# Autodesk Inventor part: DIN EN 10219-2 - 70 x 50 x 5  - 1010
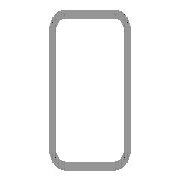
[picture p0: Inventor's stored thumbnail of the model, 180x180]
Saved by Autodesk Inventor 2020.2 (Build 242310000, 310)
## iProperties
_CCFamilyMember: 17
_CCFamilyDisplayName: DIN EN 10219-2 (Rechteckiges Hohlprofil - Kaltgeformt) - Kaltgeformte, geschweißte Baustahl-Hohlprofile aus unlegiertem Feinkorn-Baustahl
_FrameMemberDoc: Frame Member File
_Version: 15.0.0
_GetPNFromCC: 1
Created: 2019-01
Part Number: DIN EN 10219-2 - 70 x 50 x 5  - 1010
Material: Stahl, weich
Description: Kaltgeformte, geschweißte Baustahl-Hohlprofile aus unlegiertem Feinkorn-Baustahl
Document SubType Name: Modeling
Standard: DIN
Designer: lutzd
Standard Revision: 2006-07
Standards Organization: DIN
Language: de-DE
Size Designation: 70 x 50 x 5
Categories: <MemberInstance><Categories><Category DisplayName="Profile" InternalName="089c4875-fa83-4c05-b084-43b9cc11f5ed" Mnemonic="GRDR"><CategoryParameter DisplayName="
Stock Number: 70 x 50 x 5
Mass: 8208.18 g
Surface Area: 4205.32 cm^2
Volume: 1045.63 cm^3
Density: 7.85 g/cm^3
Appearance: Semi-Polished(8)
G_L: 1010,000 mm
G_W: 50,000 mm
G_H: 70,000 mm
DocNumber: ADSK-014374
Folder: .
Mass: 8,208 kg
VLT_Material: Stahl, weich
+F87BCFAC-049D-4AF7-812F-EB7A9C2FA896+SCHNITTDETAIL1: Schnittwinkel 90,00 grd
+55874402-68F4-4B5A-B811-96521EF574D8+SCHNITTDETAIL2: Schnittwinkel 90,00 grd
Dimensions: 50x70x1010 mm
IsCustomPart: 1
Title: Profil-Bauteil
Author: lutzd
Revision Number: -
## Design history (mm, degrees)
node "Startebene"
node "Endebene"
sketch "Skizze"
  geometry: L1 (-25, -25)-(-25, 25); L2 (-15, 35)-(15, 35); L3 (25, 25)-(25, -25); L4 (15, -35)-(-15, -35); L5 (-15, 30)-(15, 30); L6 (20, 25)-(20, -25); L7 (15, -30)-(-15, -30); L8 (-20, -25)-(-20, 25); L9 (0, 51.899)-(0, -51.899) reference; L10 (-37.899, 0)-(37.899, 0) reference; A1 r 10 centre (-15, -25) between (-25, -25) and (-15, -35); A2 r 10 centre (-15, 25) between (-15, 35) and (-25, 25); A3 r 10 centre (15, 25) between (25, 25) and (15, 35); A4 r 10 centre (15, -25) between (15, -35) and (25, -25); A5 r 5 centre (-15, 25) between (-15, 30) and (-20, 25); A6 r 5 centre (15, 25) between (20, 25) and (15, 30); A7 r 5 centre (15, -25) between (15, -30) and (20, -25); A8 r 5 centre (-15, -25) between (-20, -25) and (-15, -30)
  constraints: 16 end point, 16 point on circle, 8 centre point, 8 tangent, 4 parallel, 3 equal radius, 2 perpendicular, 7 other
  dimensions: "d7" = 10 radius of A1 (= G_IR); "d10" = 70 distance between parallel lines of L2 L4 (= G_H); "d11" = 50 distance between parallel lines of L1 L3 (= G_W); "d12" = 5 distance between parallel lines of L3 L6 (= G_T); "d15" = 35 distance between parallel lines of L2 L10 (= 0.5 x d10); "d16" = 25 distance between parallel lines of L9 L3 (= 0.5 x d11)
extrude "Körper" new body sketch "Skizze" stored distance "d3" = 1010 (= G_L); taper "d4" = 0 deg
node "Driven Length"
  sketch "Sketch3"
    geometry: L1 (0, 0)-(10, 0) reference
    constraints: 2 end point, 1 horizontal
  workplane "Work Plane3"
  sketch "Sketch4"
    geometry: L1 (-2, 50)-(12, 50) reference; L2 (-2, 1060)-(12, 1060) reference
    dimensions: "d18" = 1010 distance between parallel lines of L1 L2 (derived)
workplane "Arbeitsebene4"
feature "Trennen1"
workplane "Arbeitsebene5"
feature "Trennen2"
sketch "Skizze5"
  geometry: L1 (0, -50)-(0, 0) reference; L2 (0, -25)-(722, -25); 3 further points
  constraints: 2 end point, 1 coincident, 1 horizontal, 1 midpoint, 1 point on line
  dimensions: "d19" = 80 distance of point (642, -25) point (722, -25); "d20" = 722 distance of L2.start L2.end
hole "Bohrung1" sketch "Skizze5" at (722, -25), (642, -25) diameter "d21" = 6.647; stored, may be unused: countersink angle "d25" = 90 deg, drill point angle "d27" = 118 deg; dims "d22" = 16, "d23" = 4, "d24" = 2, "d26" = 8
body "Solid1"
other parameters: "G_W" = 50 [user parameter; used in 1 equation term], "G_H" = 70 [user parameter; used in 1 equation term], "G_T" = 5 [user parameter; used in 1 equation term], "G_IR" = 10 [user parameter; used in 1 equation term], "G_L" = 1010 (= d18) [user parameter; used in 1 equation term], "G_OFFSET_END" = -25 [user parameter; used in 1 equation term], "B_L" = 1085 [user parameter; used in 1 equation term], "d17" = 90 deg
